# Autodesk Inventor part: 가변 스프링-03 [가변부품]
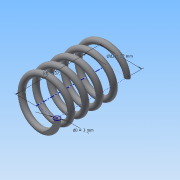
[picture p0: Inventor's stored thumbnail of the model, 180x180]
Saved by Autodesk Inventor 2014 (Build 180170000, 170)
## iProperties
Created: 2015-09
Part Number: 가변 스프링-03 [가변부품]
Material: 강철, 탄소
Document SubType Name: Modeling
Designer: study
Density: 7.87 g/cm^3
Appearance: 반연마
Mass: 18.8856 g
Surface Area: 32.5491 cm^2
Volume: 2.3997 cm^3
Author: study
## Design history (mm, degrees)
sketch "스케치1"
  geometry: L1 (0, 0)-(11, 0); L2 (11, 0)-(11, 36.411); L3 (11, 36.411)-(0, 36.411); L4 (0, 36.411)-(0, 0); C1 r 1.5 at (11, 0)
  constraints: 8 end point, 2 parallel, 1 centre point, 1 coincident, 1 horizontal, 1 perpendicular
  dimensions: "d0" = 3 diameter of C1; "d1" = 36.4112 distance of L3.end L1.start (derived); "d2" = 22 diameter of L2 L4
feature "코일1" sketch "스케치1" pitch "d3" = 10; turns "d5" = 5; dims "d4" = 36.4112 (= d1), "d6" = 0, angle "d7" = 90 deg, angle "d8" = 90 deg, "d9" = 0, "d10" = 0
sketch "스케치2"
  geometry: L1 (-12.5, 0)-(-9.5, 0) reference; 1 further point
  constraints: 1 horizontal alignment
extrude "돌출1" cut sketch "스케치2" stored distance "d11" = 10; taper "d12" = 0 deg
node "작업 평면1"
sketch "스케치3"
  geometry: L1 (-9.5, 0)-(-12.5, 0) reference; 1 further point
  constraints: 1 horizontal alignment
extrude "돌출2" cut sketch "스케치3" stored distance "d14" = 10; taper "d15" = 0 deg
node "솔리드1"
node "절단 모서리 투영1"
node "절단 모서리 투영2"
other parameters: "d13" = 36.4112 (= d1)
